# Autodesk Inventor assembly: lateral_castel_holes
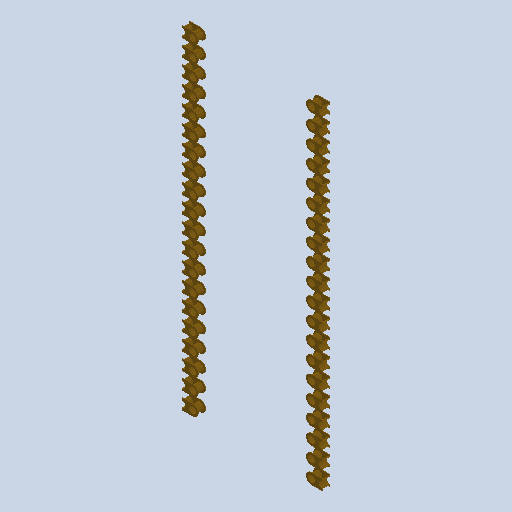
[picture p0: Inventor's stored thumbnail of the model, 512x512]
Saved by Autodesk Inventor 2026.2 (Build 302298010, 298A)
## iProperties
Created: 2026-10
Part Number: lateral_castel_holes
Document SubType Name: Assembly
Designer: mel
Author: mel
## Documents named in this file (2)
- D:\travail\année 2026-2027\1 sti2d IT\poubelle à verre\raspberry-pico-2-microcontroller-rp2350-1.snapshot.5\raspberry_pico_2\raspberry_pico_2\lateral_castel_holes.iam
- D:\travail\année 2026-2027\1 sti2d IT\poubelle à verre\raspberry-pico-2-microcontroller-rp2350-1.snapshot.5\raspberry_pico_2\raspberry_pico_2\Array.iam
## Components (2 placed, 2 different names)
1. 2618 [sub-assembly]
2. 2619 [sub-assembly]
